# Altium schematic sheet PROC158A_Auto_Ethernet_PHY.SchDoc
size 431 x 279 mm; Date: Not shown in title block; ApprovedBy: Not shown in title block; CheckedBy: Not shown in title block; Author: Not shown in title block; CompanyName: Not shown in title block; Engineer: Not shown in title block; Organization: Not shown in title block; Address1: Not shown in title block; Address2: Not shown in title block; Address3: Not shown in title block; Address4: Not shown in title block; DocumentNumber: 14; Revision: Use project parameter SCH_Rev; SheetNumber: 14; SheetTotal: 24; PageSetup: Record=PageOptions¦CenterHorizontal=True¦CenterVertical=True¦PrintScale=1.00¦XCorrection=1.00¦YCorrection=1.00¦PrintKind=0¦BorderSize=5000000¦LeftOffset=0¦BottomOffset=0¦Orientation=2¦PaperLength=1000¦PaperWidth=1000¦Scale=100¦PaperSource=15¦PrintQuality=600¦MediaType=1¦DitherType=10¦PaperKind=Letter¦PrintScaleMode=1
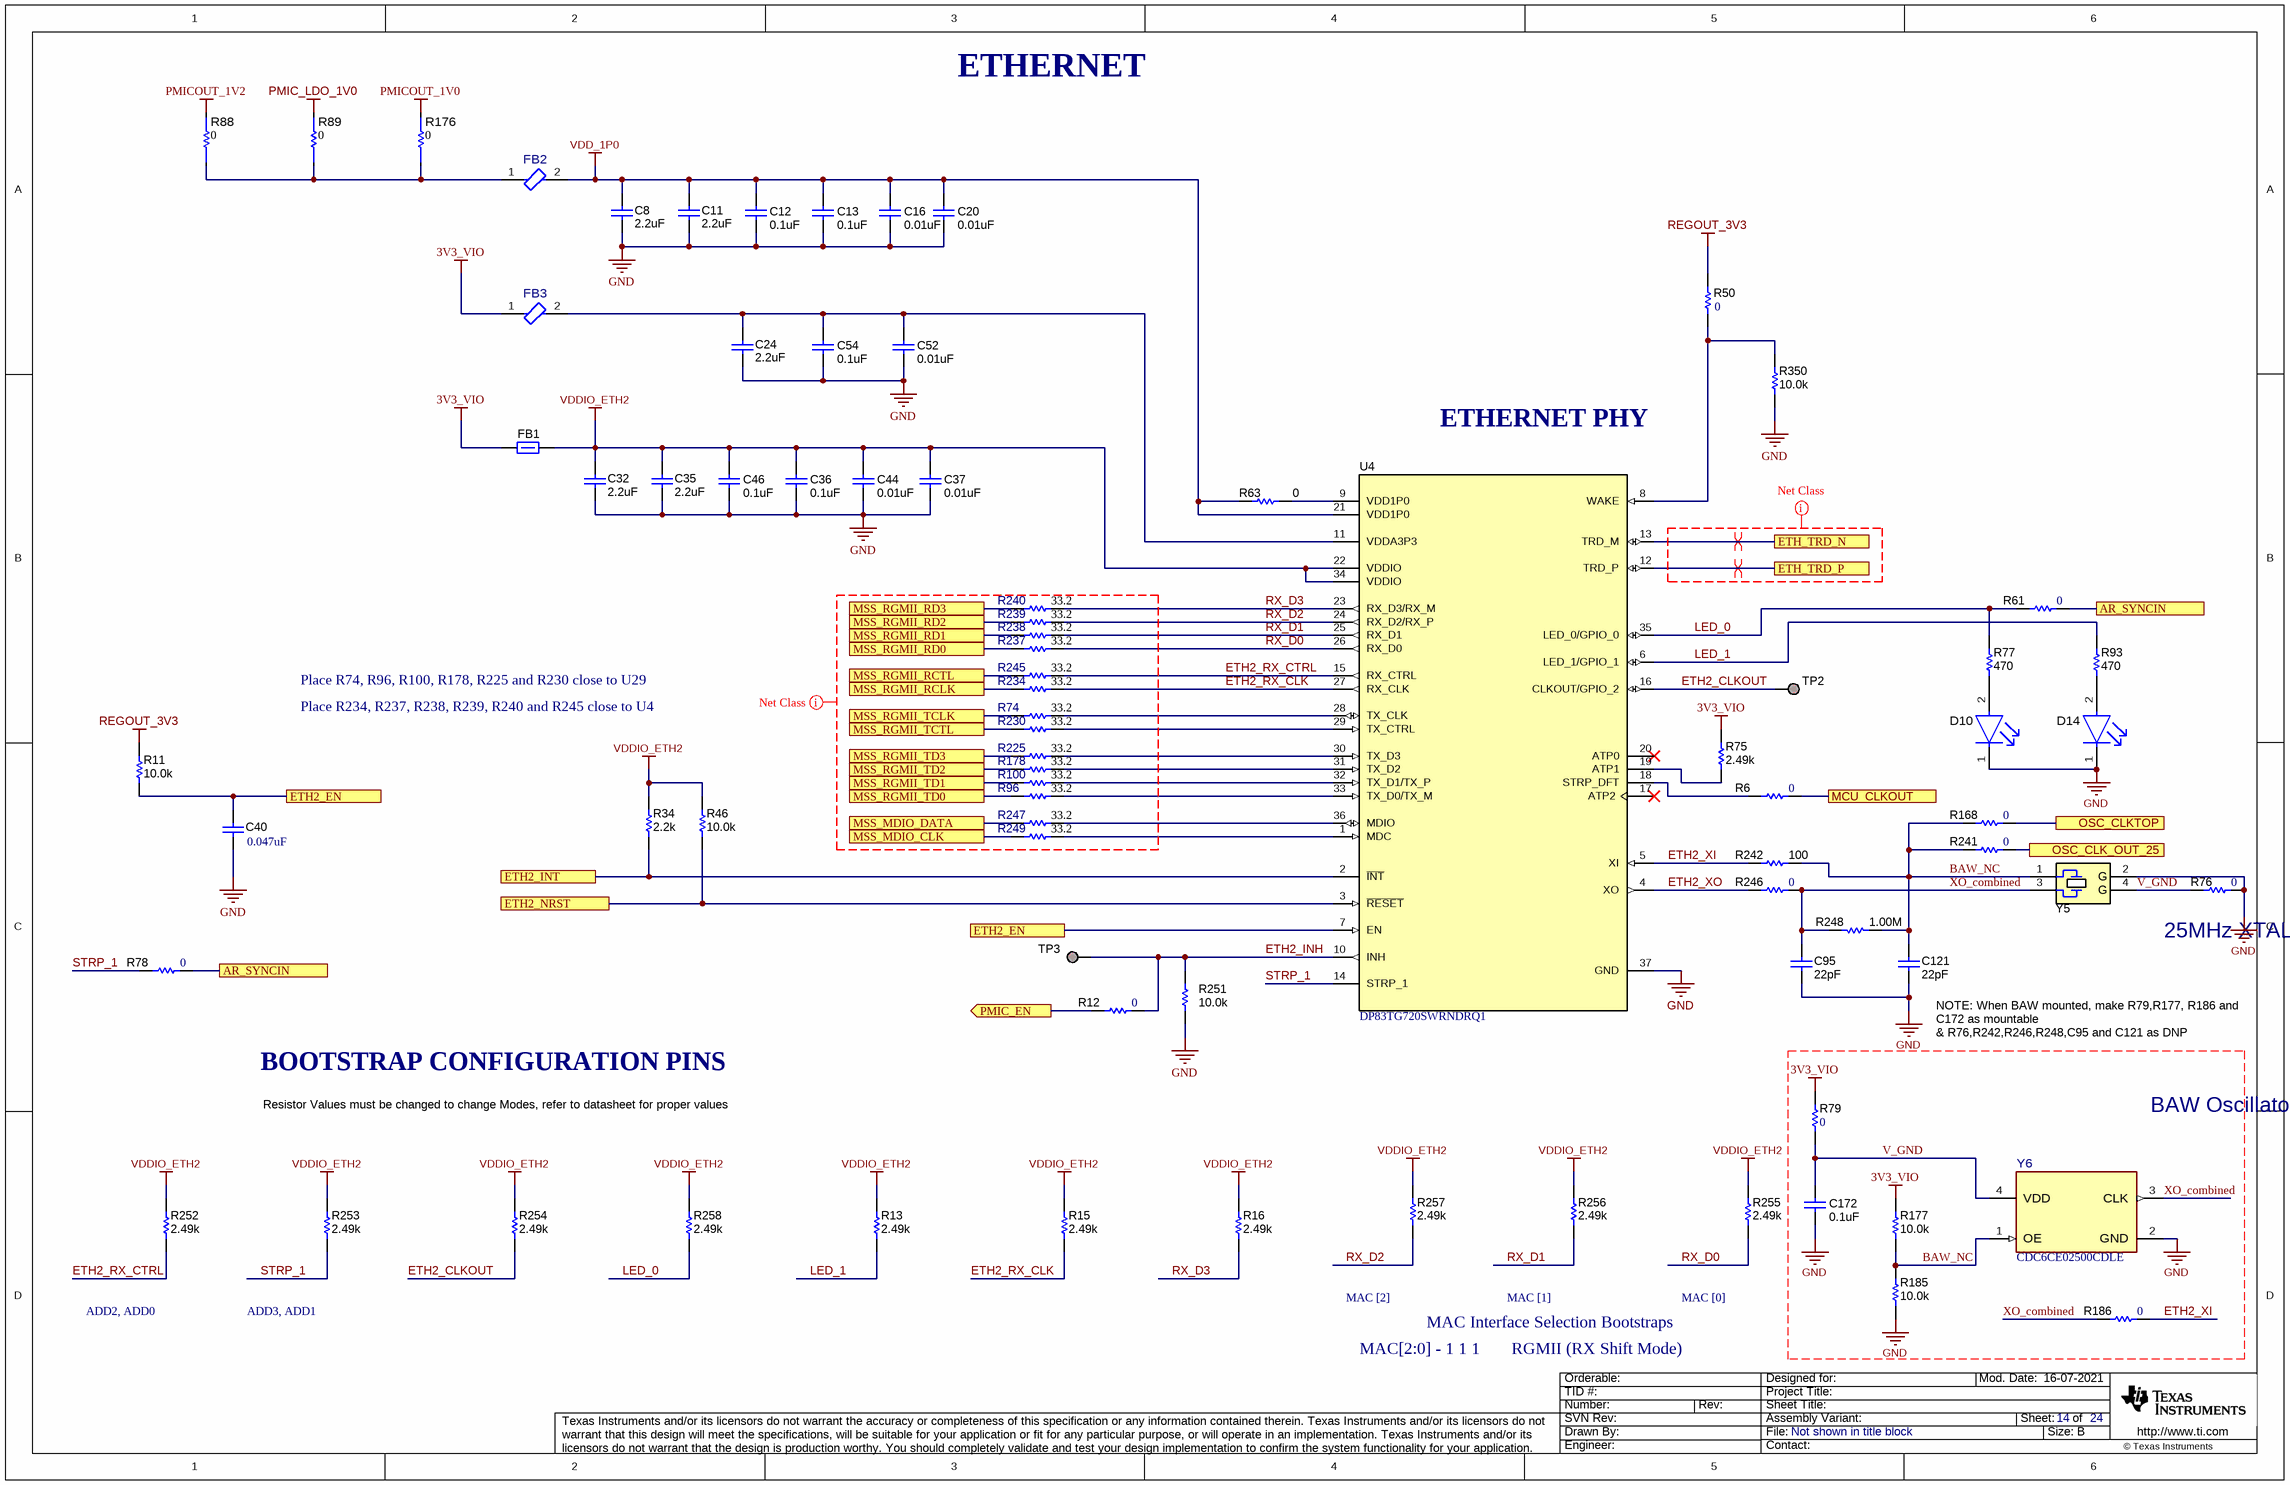
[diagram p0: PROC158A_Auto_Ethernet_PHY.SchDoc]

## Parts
C8  ValueDisplayed: 2.2uF  [0603L]  (hidden comment: GCM188R70J225KE22D)
C11  ValueDisplayed: 2.2uF  [0603L]  (hidden comment: GCM188R70J225KE22D)
C12  ValueDisplayed: 0.1uF  [0402L]  (hidden comment: GCM155R71C104KA55D)
C13  ValueDisplayed: 0.1uF  [0402L]  (hidden comment: GCM155R71C104KA55D)
C16  ValueDisplayed: 0.01uF  [0402L]  (hidden comment: CGA2B3X7R1H103K050BB)
C20  ValueDisplayed: 0.01uF  [0402L]  (hidden comment: CGA2B3X7R1H103K050BB)
C24  ValueDisplayed: 2.2uF  [0603L]  (hidden comment: GCM188R70J225KE22D)
C32  ValueDisplayed: 2.2uF  [0603L]  (hidden comment: GCM188R70J225KE22D)
C35  ValueDisplayed: 2.2uF  [0603L]  (hidden comment: GCM188R70J225KE22D)
C36  ValueDisplayed: 0.1uF  [0402L]  (hidden comment: GCM155R71C104KA55D)
C37  ValueDisplayed: 0.01uF  [0402L]  (hidden comment: CGA2B3X7R1H103K050BB)
C40  ValueDisplayed: 0.047uF  [0402]  (hidden comment: GRM155R71E473KA88D)
C44  ValueDisplayed: 0.01uF  [0402L]  (hidden comment: CGA2B3X7R1H103K050BB)
C46  ValueDisplayed: 0.1uF  [0402L]  (hidden comment: GCM155R71C104KA55D)
C52  ValueDisplayed: 0.01uF  [0402L]  (hidden comment: CGA2B3X7R1H103K050BB)
C54  ValueDisplayed: 0.1uF  [0402L]  (hidden comment: GCM155R71C104KA55D)
C95  ValueDisplayed: 22pF  [0603]  (hidden comment: CGA3E2C0G1H220J080AA)
C121  ValueDisplayed: 22pF  [0603]  (hidden comment: CGA3E2C0G1H220J080AA)
C172  ValueDisplayed: 0.1uF  [0402L]  (hidden comment: GCM155R71C104KA55D)
D10  SML-P12YTT86R  [FP-SML-P12YTT86R_0402-MFG]  (value not drawn)
D14  SML-P12DTT86R  [FP-SML-P12DTT86R_0402-MFG]  (value not drawn)
FB1  BLM18HE102SN1D  [0603]  (value not drawn)
FB2  BLM18KG601SH1  [FP-BLM18KG601SH1_0603 (1608 Metric)-MFG]  (value not drawn)
FB3  BLM18KG601SH1  [FP-BLM18KG601SH1_0603 (1608 Metric)-MFG]  (value not drawn)
R6  ValueDisplayed: 0  [0402L]  (hidden comment: ERJ-2GE0R00X)
R11  ValueDisplayed: 10.0k  [0402L]  (hidden comment: CRCW040210K0FKED)
R12  ValueDisplayed: 0  [0201L]  (hidden comment: CRCW02010000Z0ED)
R13  ValueDisplayed: 2.49k  [0402L]  (hidden comment: CRCW04022K49FKED)
R15  ValueDisplayed: 2.49k  [0402L]  (hidden comment: CRCW04022K49FKED)
R16  ValueDisplayed: 2.49k  [0402L]  (hidden comment: CRCW04022K49FKED)
R34  ValueDisplayed: 2.2k  [0402L]  (hidden comment: CRCW04022K20JNED)
R46  ValueDisplayed: 10.0k  [0402L]  (hidden comment: CRCW040210K0FKED)
R50  ValueDisplayed: 0  [0402L]  (hidden comment: ERJ-2GE0R00X)
R61  ValueDisplayed: 0  [0201L]  (hidden comment: CRCW02010000Z0ED)
R63  ValueDisplayed: 0  [0402]  (hidden comment: CRCW04020000Z0EDHP)
R74  ValueDisplayed: 33.2  [0402L]  (hidden comment: CRCW040233R2FKED)
R75  ValueDisplayed: 2.49k  [0402L]  (hidden comment: CRCW04022K49FKED)
R76  ValueDisplayed: 0  [0402L]  (hidden comment: ERJ-2GE0R00X)
R77  ValueDisplayed: 470  [0402L]  (hidden comment: ERJ-2RKF4700X)
R78  ValueDisplayed: 0  [0201L]  (hidden comment: CRCW02010000Z0ED)
R79  ValueDisplayed: 0  [0402L]  (hidden comment: ERJ-2GE0R00X)
R88  Res_ohm: 0  [FP-HCJ0603ZT0R00_0603-MFG]  (hidden comment: HCJ0603ZT0R00)
R89  Res_ohm: 0  [FP-HCJ0603ZT0R00_0603-MFG]  (hidden comment: HCJ0603ZT0R00)
R93  ValueDisplayed: 470  [0402L]  (hidden comment: ERJ-2RKF4700X)
R96  ValueDisplayed: 33.2  [0402L]  (hidden comment: CRCW040233R2FKED)
R100  ValueDisplayed: 33.2  [0402L]  (hidden comment: CRCW040233R2FKED)
R168  ValueDisplayed: 0  [0402L]  (hidden comment: ERJ-2GE0R00X)
R176  Res_ohm: 0  [FP-HCJ0603ZT0R00_0603-MFG]  (hidden comment: HCJ0603ZT0R00)
R177  ValueDisplayed: 10.0k  [0402L]  (hidden comment: CRCW040210K0FKED)
R178  ValueDisplayed: 33.2  [0402L]  (hidden comment: CRCW040233R2FKED)
R185  ValueDisplayed: 10.0k  [0402L]  (hidden comment: CRCW040210K0FKED)
R186  ValueDisplayed: 0  [0402L]  (hidden comment: ERJ-2GE0R00X)
R225  ValueDisplayed: 33.2  [0402L]  (hidden comment: CRCW040233R2FKED)
R230  ValueDisplayed: 33.2  [0402L]  (hidden comment: CRCW040233R2FKED)
R234  ValueDisplayed: 33.2  [0402L]  (hidden comment: CRCW040233R2FKED)
R237  ValueDisplayed: 33.2  [0402L]  (hidden comment: CRCW040233R2FKED)
R238  ValueDisplayed: 33.2  [0402L]  (hidden comment: CRCW040233R2FKED)
R239  ValueDisplayed: 33.2  [0402L]  (hidden comment: CRCW040233R2FKED)
R240  ValueDisplayed: 33.2  [0402L]  (hidden comment: CRCW040233R2FKED)
R241  ValueDisplayed: 0  [0402L]  (hidden comment: ERJ-2GE0R00X)
R242  ValueDisplayed: 100  [0402L]  (hidden comment: ERJ-2GEJ101X)
R245  ValueDisplayed: 33.2  [0402L]  (hidden comment: CRCW040233R2FKED)
R246  ValueDisplayed: 0  [0402L]  (hidden comment: ERJ-2GE0R00X)
R247  ValueDisplayed: 33.2  [0402L]  (hidden comment: CRCW040233R2FKED)
R248  ValueDisplayed: 1.00M  [0603L]  (hidden comment: CRCW06031M00FKEA)
R249  ValueDisplayed: 33.2  [0402L]  (hidden comment: CRCW040233R2FKED)
R251  ValueDisplayed: 10.0k  [0402L]  (hidden comment: CRCW040210K0FKED)
R252  ValueDisplayed: 2.49k  [0402L]  (hidden comment: CRCW04022K49FKED)
R253  ValueDisplayed: 2.49k  [0402L]  (hidden comment: CRCW04022K49FKED)
R254  ValueDisplayed: 2.49k  [0402L]  (hidden comment: CRCW04022K49FKED)
R255  ValueDisplayed: 2.49k  [0402L]  (hidden comment: CRCW04022K49FKED)
R256  ValueDisplayed: 2.49k  [0402L]  (hidden comment: CRCW04022K49FKED)
R257  ValueDisplayed: 2.49k  [0402L]  (hidden comment: CRCW04022K49FKED)
R258  ValueDisplayed: 2.49k  [0402L]  (hidden comment: CRCW04022K49FKED)
R350  ValueDisplayed: 10.0k  [0402L]  (hidden comment: CRCW040210K0FKED)
TP2  TESTPOINT  [TP_25MIL-SMT]  (value not drawn)  (no BOM)
TP3  TESTPOINT  [TP_25MIL-SMT]  (value not drawn)  (no BOM)
U4  DP83TG720SWRNDRQ1  [RND0036A]
Y5  ABM8AIG-25.000MHZ-12-2Z-T3  [Abracon_ABM8AIG]  (value not drawn)
Y6  CDC6CE02500CDLE  [DLE0004A-MFG]

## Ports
AR_SYNCIN, ETH2_EN, ETH2_INT, ETH2_NRST, ETH_TRD_N, ETH_TRD_P, MCU_CLKOUT, MSS_MDIO_CLK, MSS_MDIO_DATA, MSS_RGMII_RCLK, MSS_RGMII_RCTL, MSS_RGMII_RD0, MSS_RGMII_RD1, MSS_RGMII_RD2, MSS_RGMII_RD3, MSS_RGMII_TCLK, MSS_RGMII_TCTL, MSS_RGMII_TD0, MSS_RGMII_TD1, MSS_RGMII_TD2, MSS_RGMII_TD3, OSC_CLK_OUT_25, OSC_CLKTOP, PMIC_EN (out)

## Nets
3V3_VIO: FB1.1 FB3.1 R75.2 R79.1 R177.1
GND: C8.1 C11.1 C12.1 C13.1 C16.2 C20.2 C24.1 C32.1 C35.1 C36.1 C37.2 C40.2 C44.2 C46.1 C52.2 C54.1 C95.2 C121.2 C172.1 D10.1(CATHODE) D14.1(CATHODE) R76.1 R185.2 R251.2 R350.2 U4.37(GND) Y5.2(GND) Y6.2(GND)
PMIC_LDO_1V0: R89.2
PMICOUT_1V0: R176.2
PMICOUT_1V2: R88.2
REGOUT_3V3: R11.1 R50.2
VDD_1P0: C8.2 C11.2 C12.2 C13.2 C16.1 C20.1 FB2.2 R63.1 U4.21(VDD1P0)
VDDIO_ETH2: C32.2 C35.2 C36.2 C37.1 C44.1 C46.2 FB1.2 R13.2 R15.2 R16.2 R34.1 R46.1 R252.2 R253.2 R254.2 R255.2 R256.2 R257.2 R258.2 U4.22(VDDIO) U4.34(VDDIO)
AR_SYNCIN: R61.2 R78.2 ; port AR_SYNCIN
BAW_NC: C121.1 R168.2 R177.2 R185.1 R241.2 R242.2 R248.1 Y5.1 Y6.1(OE)
ETH2_CLKOUT: R254.1 TP2.1 U4.16(CLKOUT/GPIO_2)
ETH2_EN: C40.1 R11.2 U4.7(EN) ; port ETH2_EN
ETH2_INH: R12.2 R251.1 TP3.1 U4.10(INH)
ETH2_INT: R34.2 U4.2(~{INT}) ; port ETH2_INT
ETH2_NRST: R46.2 U4.3(~{RESET}) ; port ETH2_NRST
ETH2_RX_CLK: R15.1 R234.2 U4.27(RX_CLK)
ETH2_RX_CTRL: R245.2 R252.1 U4.15(RX_CTRL)
ETH2_XI: R186.1 R242.1 U4.5(XI)
ETH2_XO: R246.2 U4.4(XO)
ETH_TRD_N: U4.13(TRD_M) ; port ETH_TRD_N
ETH_TRD_P: U4.12(TRD_P) ; port ETH_TRD_P
LED_0: R61.1 R77.2 R258.1 U4.35(LED_0/GPIO_0)
LED_1: R13.1 R93.2 U4.6(LED_1/GPIO_1)
MCU_CLKOUT: R6.1 ; port MCU_CLKOUT
MSS_MDIO_CLK: R249.1 ; port MSS_MDIO_CLK
MSS_MDIO_DATA: R247.1 ; port MSS_MDIO_DATA
MSS_RGMII_RCLK: R234.1 ; port MSS_RGMII_RCLK
MSS_RGMII_RCTL: R245.1 ; port MSS_RGMII_RCTL
MSS_RGMII_RD0: R237.1 ; port MSS_RGMII_RD0
MSS_RGMII_RD1: R238.1 ; port MSS_RGMII_RD1
MSS_RGMII_RD2: R239.1 ; port MSS_RGMII_RD2
MSS_RGMII_RD3: R240.1 ; port MSS_RGMII_RD3
MSS_RGMII_TCLK: R74.1 ; port MSS_RGMII_TCLK
MSS_RGMII_TCTL: R230.1 ; port MSS_RGMII_TCTL
MSS_RGMII_TD0: R96.1 ; port MSS_RGMII_TD0
MSS_RGMII_TD1: R100.1 ; port MSS_RGMII_TD1
MSS_RGMII_TD2: R178.1 ; port MSS_RGMII_TD2
MSS_RGMII_TD3: R225.1 ; port MSS_RGMII_TD3
OSC_CLK_OUT_25: R241.1 ; port OSC_CLK_OUT_25
OSC_CLKTOP: R168.1 ; port OSC_CLKTOP
PMIC_EN: R12.1 ; port PMIC_EN
RX_D0: R237.2 R255.1 U4.26(RX_D0)
RX_D1: R238.2 R256.1 U4.25(RX_D1)
RX_D2: R239.2 R257.1 U4.24(RX_D2/RX_P)
RX_D3: R16.1 R240.2 U4.23(RX_D3/RX_M)
STRP_1: R78.1 R253.1 U4.14(STRP_1)
V_GND: C172.2 R76.2 R79.2 Y5.4(GND) Y6.4(VDD)
XO_combined: C95.1 R186.2 R246.1 R248.2 Y5.3 Y6.3(CLK)
NetC24_2: C24.2 C52.1 C54.2 FB3.2 U4.11(VDDA3P3)
NetD10_2: D10.2(ANODE) R77.1
NetD14_2: D14.2(ANODE) R93.1
NetFB2_1: FB2.1 R88.1 R89.1 R176.1
NetR6_2: R6.2 U4.18(STRP_DFT)
NetR50_1: R50.1 R350.1 U4.8(WAKE)
NetR63_2: R63.2 U4.9(VDD1P0)
NetR74_2: R74.2 U4.28(TX_CLK)
NetR75_1: R75.1 U4.19(ATP1)
NetR96_2: R96.2 U4.33(TX_D0/TX_M)
NetR100_2: R100.2 U4.32(TX_D1/TX_P)
NetR178_2: R178.2 U4.31(TX_D2)
NetR225_2: R225.2 U4.30(TX_D3)
NetR230_2: R230.2 U4.29(TX_CTRL)
NetR247_2: R247.2 U4.36(MDIO)
NetR249_2: R249.2 U4.1(MDC)

Not connected (* = marked no-connect by the designer): U4 17(ATP2)* 20(ATP0)*

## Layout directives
differential pair: ETH_TRD_N, ETH_TRD_P
net class RGMII: (no net found under the mark)

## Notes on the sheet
- ETHERNET
- ETHERNET PHY
- Place R74, R96, R100, R178, R225 and R230 close to U29
- Place R234, R237, R238, R239, R240 and R245 close to U4
- (near Y5) 25MHz XTAL
- (near C121) NOTE: When BAW mounted, make R79,R177, R186 and C172 as mountable
  & R76,R242,R246,R248,C95 and C121 as DNP
- BOOTSTRAP CONFIGURATION PINS
- Resistor Values must be changed to change Modes, refer to datasheet for proper values
- BAW Oscillator
- MAC [2]
- MAC [1]
- MAC [0]
- ADD2, ADD0
- ADD3, ADD1
- MAC[2:0] - 1 1 1       RGMII (RX Shift Mode)
- MAC Interface Selection Bootstraps

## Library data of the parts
C8 C11 C24 C32 C35 = CMP-0007134-5: CAP, CERM, 2.2 uF, 6.3 V, +/- 10%, X7R, AEC-Q200 Grade 1, 0603; Manufacturer: MuRata; TaMin_C: -55°C; Polarized: N; SizeAreaWB_mm2: 4.68; Value1: Unknown; U/M: EA; Value: 2.2uF; TaMax_C: 125°C; SizeZ_mm: 1; SizeX_mm: 1.6; SizeY_mm: 0.8; Cap_Case: 0603; Value2: 6.3V; SizeArea_mm2: 1.28; AEC Qualified: Y; Cap_F: 2.2µF; AEC Category: Q200
C12 C13 C36 C46 C54 C172 = CMP-0006351-2: CAP, CERM, 0.1 uF, 16 V, +/- 10%, X7R, 0402; Manufacturer: MuRata; TaMin_C: -55°C; Polarized: N; SizeAreaWB_mm2: 3; Value1: Unknown; U/M: EA; Value: 0.1uF; TaMax_C: 125°C; SizeZ_mm: 0.6; SizeX_mm: 1; SizeY_mm: 0.5; Cap_Case: 0402; Value2: 16V; CompType: Capacitor; Cap_F: 100nF; AEC Category: Q200
C16 C20 C37 C44 C52 = CMP-0006324-2: CAP, CERM, 0.01 uF, 50 V, +/- 10%, X7R, AEC-Q200 Grade 1, 0402; Manufacturer: TDK; TaMin_C: -55°C; ESR_ohm: 0.333065; Polarized: N; SizeAreaWB_mm2: 3; Value1: 0.333065 ohm; U/M: EA; Value: 0.01uF; TaMax_C: 125°C; SizeZ_mm: 0.6; SizeX_mm: 1; SizeY_mm: 0.5; Cap_Case: 0402; Value2: 50V; CompType: Capacitor; AEC Qualified: Y; Cap_F: 10nF; IRMS_A: 323.373mA; AEC Category: Q200
C40 = CMP-0006669-2: CAP, CERM, 0.047 uF, 25 V, +/- 10%, X7R, 0402; Manufacturer: MuRata; TaMin_C: -55°C; Polarized: N; SizeAreaWB_mm2: 3; Value1: Unknown; U/M: EA; TaMax_C: 125°C; SizeZ_mm: 0.6; SizeX_mm: 1; SizeY_mm: 0.5; Value2: 25V; Cap_F: 47nF; AEC Category: Q200
C95 C121 = CMP-0007071-4: CAP, CERM, 22 pF, 50 V, +/- 5%, C0G/NP0, AEC-Q200 Grade 1, 0603; Manufacturer: TDK; TaMin_C: -55°C; Polarized: N; SizeAreaWB_mm2: 4.68; Value1: Unknown; U/M: EA; Value: 22pF; TaMax_C: 125°C; SizeZ_mm: 1; SizeX_mm: 1.6; SizeY_mm: 0.8; Value2: 50V; SizeArea_mm2: 1.28; CompType: Capacitor; AEC Qualified: Y; AEC Category: Q200
D10 = CMP-0120222-1: Yellow 590nm LED Indication - Discrete 2.1V 0402 (1006 Metric); Manufacturer: Rohm Semiconductor; Power_TotalModule: 52mW; SizeZ_mm: 0.25mm; Tjmax_C: 110°C; Vr_V: 5V; AEC Qualified: No; Forward Current: 20mA; Led Orientation: Top View; Luminous Intensity: 100mcd
D14 = CMP-0120221-1: LED Uni-Color Orange 2-Pin Chip 0402(1006Metric) T/R; Manufacturer: Rohm Semiconductor; LambdaD: 605nm; Power_TotalModule: 52mW; SizeZ_mm: 0.25mm; Tjmax_C: 110°C; Vf_V: 2.1V; Vr_V: 5V; AEC Qualified: No; Forward Current: 20mA; Led Orientation: Top View; Luminous Intensity: 100mcd
FB1 = CMP-0003348-2: Ferrite Bead, 1000 ohm @ 100 MHz, 0.6 A, 0603; Manufacturer: MuRata; Ztyp@1GHz_Ohm: 1k; SizeAreaWB_mm2: 4.68; DCR_ohm: 3.5d; Value1: 0.35 ohm; Imax_A: 6dA; SizeZ_mm: 1; SizeX_mm: 1.6; SizeY_mm: 0.8; Value2: 0.6A; SizeArea_mm2: 1.28
FB2 FB3 = CMP-0089848-1: 600 Ohms @ 100MHz 1 Power Line Ferrite Bead 0603 (1608 Metric) 1.3A 150mOhm; Manufacturer: Murata; Tolerance_%: 25%; SizeZ_mm: 0.95mm; Impedance At Frequency: 600Ω @ 100MHz; AEC Qualified: Yes; AEC Grade: Grade 1; DCR_ohm: 0.15
R6 R50 R76 R79 R168 R186 R241 R246 = CMP-0026992-3: RES, 0, 5%, 0.1 W, AEC-Q200 Grade 0, 0402; Manufacturer: Panasonic; Power_W: 100mW; TempCo: 600 ppm/C; Value_Code: 0000; Value: 0; EIA_Code: E24; SizeX_mm: 1; SizeY_mm: 0.5; SizeZ_mm: 0.6; Value2: 0.1W; AEC Qualified: Y; VDC_V: 50V; AEC Category: Q200; SizeAreaWB_mm2: 3
R11 R46 R177 R185 R251 R350 = CMP-0025958-3: RES, 10.0 k, 1%, 0.063 W, AEC-Q200 Grade 0, 0402; Manufacturer: Vishay-Dale; Power_W: 63mW; TempCo: 100 ppm/C; Value_Code: 10k0; Value: 10.0k; EIA_Code: E96; Res_ohm: 10k; SizeX_mm: 1; SizeY_mm: 0.5; SizeZ_mm: 0.6; Value2: 0.063W; CompType: Resistor; AEC Qualified: Y; VDC_V: 50V; AEC Category: Q200; AEC Grade: 0
R12 R61 R78 = CMP-0027008-4: RES, 0, 5%, 0.05 W, 0201; Manufacturer: Vishay-Dale; Power_W: 50mW; TempCo: ppm/C; Value_Code: 0000; Value: 0; EIA_Code: E24; SizeX_mm: 0.6; SizeY_mm: 0.3; SizeZ_mm: 0.26; Value2: 0.05W; SizeArea_mm2: 0.18; AEC Qualified: N; AEC Category: Q200
R13 R15 R16 R75 R252-R258 = CMP-0026237-2: RES, 2.49 k, 1%, 0.063 W, AEC-Q200 Grade 0, 0402; Manufacturer: Vishay-Dale; Power_W: 63mW; TempCo: 100 ppm/C; Value_Code: 2k49; Value: 2.49k; EIA_Code: E96; SizeX_mm: 1; SizeY_mm: 0.5; SizeZ_mm: 0.6; Value2: 0.063W; AEC Qualified: Y; VDC_V: 50V; AEC Category: Q200; AEC Grade: 0
R34 = CMP-0026890-5: RES, 2.2 k, 5%, 0.063 W, AEC-Q200 Grade 0, 0402; Manufacturer: Vishay-Dale; Power_W: 63mW; TempCo: 200 ppm/C; Value_Code: 2k20; Value: 2.2k; EIA_Code: E24; SizeX_mm: 1; SizeY_mm: 0.5; SizeZ_mm: 0.6; Value2: 0.063W; AEC Qualified: Y; VDC_V: 50V; AEC Category: Q200; AEC Grade: 0
R63 = CMP-0081856-1: RES, 0, 0%, 0.2 W, AEC-Q200 Grade 0, 0402; Manufacturer: Vishay-Dale; SizeAreaWB_mm2: 3; SizeArea_mm2: 0.5; AEC Qualified: Y; AEC Category: Q200; Value: 0; SizeZ_mm: 0.6; Power_W: 200mW; VDC_V: 50V; Value2: 0.2W; SizeX_mm: 1
R74 R96 R100 R178 R225 R230 R234 R237-R240 R245 R247 R249 = CMP-0026299-2: RES, 33.2, 1%, 0.063 W, AEC-Q200 Grade 0, 0402; Manufacturer: Vishay-Dale; Power_W: 63mW; TempCo: 100 ppm/C; Value_Code: 33R2; Value: 33.2; EIA_Code: E96; SizeX_mm: 1; SizeY_mm: 0.5; SizeZ_mm: 0.6; Value2: 0.063W; AEC Qualified: Y; VDC_V: 50V; AEC Category: Q200; AEC Grade: 0
R77 R93 = CMP-0026699-1: RES, 470, 1%, 0.1 W, AEC-Q200 Grade 0, 0402; Manufacturer: Panasonic; Power_W: 100mW; TempCo: 100 ppm/C; Value_Code: 470R; U/M: EA; Value: 470; SizeX_mm: 1; SizeY_mm: 0.5; SizeZ_mm: 0.6; Value2: 0.1W; AEC Qualified: Y; VDC_V: 50V; AEC Grade: 0; AEC Category: Q200
R88 R89 R176 = CMP-0091690-1: RES 0 OHM JUMPER 1/4W 0603; Manufacturer: Stackpole Electronics; Power_W: 250mW; AEC Grade: Grade 0; AEC Qualified: Yes; SizeZ_mm: 0.7mm; Value: 0
R242 = CMP-0026993-2: RES, 100, 5%, 0.1 W, AEC-Q200 Grade 0, 0402; Manufacturer: Panasonic; Power_W: 100mW; TempCo: 200 ppm/C; Value_Code: 100R; U/M: EA; Value: 100; EIA_Code: E24; SizeX_mm: 1; SizeY_mm: 0.5; SizeZ_mm: 0.6; Value2: 0.1W; AEC Qualified: Y; AEC Grade: 0; AEC Category: Q200
R248 = CMP-0022138-4: RES, 1.00 M, 1%, 0.1 W, AEC-Q200 Grade 0, 0603; Manufacturer: Vishay-Dale; Power_W: 100mW; TempCo: 100 ppm/C; Value_Code: 1M00; Value: 1.00Meg; EIA_Code: E96; Res_ohm: 1M; SizeX_mm: 1.6; SizeY_mm: 0.8; SizeZ_mm: 1; Value2: 0.1W; SizeArea_mm2: 1.28; AEC Qualified: Y; VDC_V: 75V; AEC Category: Q200; AEC Grade: 0
TP2 TP3 = CMP-0078143-3: TEST POINT.  No entry in BOM.
U4 = CMP-0085268-1: Low Power Auto PHY 1000BASE-T1 Automotive Ethernet Physical Layer Transceiver, RND0036A (VQFNP-36); Alternate Manufacturer: Texas Instruments; Alternate PartNumber: DP83TG720SWRNDTQ1; SizeY_mm: 6; SizeAreaWB_mm2: 64; SizeZ_mm: 0.9; AEC Qualified: Y; SizeArea_mm2: 36; AEC Category: Q200; CompType: IC
Y5 = CMP-0004682-5: Crystal, 25 MHz, 12pF, AEC-Q200 Grade 1, SMD; Manufacturer: Abracon Corporation; TaMin_C: -40°C; Frequency Stability: 50 ppm; SizeAreaWB_mm2: 14.7; Frequency_Fixed: 25MHz; TaMax_C: 125°C; SizeZ_mm: 0.8; SizeX_mm: 2.5; SizeY_mm: 3.2; SizeArea_mm2: 8; AEC Category: Q200; AEC Grade: 1; AEC Qualified: Y
Y6 = CMP-0001498-1: Low Jitter, Low Power, LVCMOS Output, BAW Oscillator; Manufacturer: Texas Instruments; SizeZ_mm: 1mm; AEC Qualified: Yes; AEC Grade: Grade 1; Frequency Stability: 20ppm; Frequency_Fixed: 25MHz; Max Supply Current: 5mA; Max Supply Voltage: 3.63V; Min Supply Voltage: 1.62V; Standoff Height: 0mm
